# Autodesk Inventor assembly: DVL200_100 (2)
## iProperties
Created: 2009-09
Part Number: DVL200_100 (2)
Document SubType Name: Assembly
Designer: TB
Mass: 14667.2 g
Surface Area: 10998.5 cm^2
Volume: 14667.2 cm^3
Density: 1 g/cm^3
Description: KM DVL 200/100 - 100 mm
Slaglengde: 100.000 mm
Author: TB
